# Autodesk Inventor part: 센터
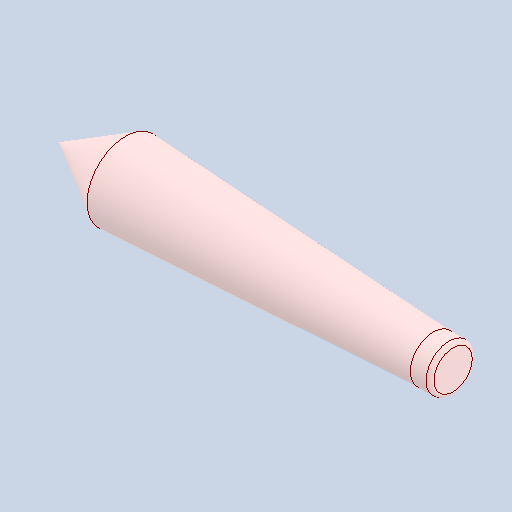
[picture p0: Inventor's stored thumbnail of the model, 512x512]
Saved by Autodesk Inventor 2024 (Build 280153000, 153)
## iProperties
Created: 2024-07
Part Number: 센터
Material: 강철, 합금
Document SubType Name: Modeling
Designer: com
Density: 7.73 g/cm^3
Appearance: 기본값
Author: jhkim
Sending System: Autodesk Inventor 2025
Preprocessor: ST-DEVELOPER v20
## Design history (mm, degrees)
feature "솔리드1"
node "솔리드2"
